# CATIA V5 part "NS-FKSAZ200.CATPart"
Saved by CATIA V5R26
Part number: NS-FKSAZ200
Bounding box of the stored display mesh (mm): x -120.601 to 120.601, y -249.867 to 0, z -57.2 to 55.6
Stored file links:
  R:\Document\坂尻\その他\ナベヤデータ変換\安全カバーキャスター\MCBKSAZ200\NS-FKSAZ200.CATPart
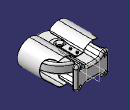
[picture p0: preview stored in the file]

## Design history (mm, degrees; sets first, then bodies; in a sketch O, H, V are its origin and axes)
Body1 (main body)
  Solid1: solid without history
